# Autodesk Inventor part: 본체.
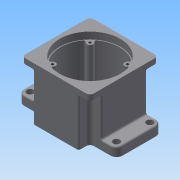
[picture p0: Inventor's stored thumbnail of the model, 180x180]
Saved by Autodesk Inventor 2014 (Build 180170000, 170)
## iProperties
Created: 2015-06
Part Number: 본체.
Material: 일반
Document SubType Name: Modeling
Designer: AMC
Density: 1 g/cm^3
Appearance: 기본값
Author: AMC
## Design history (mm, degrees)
sketch "스케치1"
  geometry: L1 (0, 0)-(30, 0); L2 (30, 0)-(30, 15); L3 (30, 15)-(65, 15); L4 (65, 15)-(65, 75); L5 (65, 75)-(30, 75); L6 (30, 75)-(30, 90); L7 (30, 90)-(0, 90); L8 (0, 90)-(0, 0); L9 (0, 0)-(-30, 0); L10 (-30, 0)-(-30, 15); L11 (-30, 15)-(-65, 15); L12 (-65, 15)-(-65, 75); L13 (-65, 75)-(-30, 75); L14 (-30, 75)-(-30, 90); L15 (-30, 90)-(0, 90)
  constraints: 30 end point, 6 symmetric about line, 5 parallel, 1 collinear, 1 horizontal, 1 perpendicular
  dimensions: "d0" = 130 diameter of L4 L8; "d1" = 60 diameter of L6 L8; "d2" = 60 diameter of L2 L8; "d3" = 60 distance between parallel lines of L5 L3; "d4" = 90 distance between parallel lines of L1 L7; "d5" = 15 distance between parallel lines of L1 L3
extrude "돌출1" new body sketch "스케치1" distance "d6" = 12; taper "d7" = 0 deg
sketch "스케치2"
  geometry: L1 (30, 90)-(-30, 90) reference; L2 (-30, 90)-(-30, 75) reference; L3 (-30, 75)-(-65, 75) reference; L4 (-65, 15)-(-30, 15) reference; L5 (-30, 15)-(-30, 0) reference; L6 (-30, 0)-(30, 0) reference; L7 (30, 0)-(30, 15) reference; L8 (30, 15)-(65, 15) reference; L9 (65, 75)-(30, 75) reference; L10 (30, 75)-(30, 90) reference; L11 (-45, 75)-(-45, 15); L12 (45, 75)-(45, 15); 1 further point
  constraints: 4 end point, 4 point on line, 2 perpendicular
  dimensions: "d8" = 45 distance from line of L12 point (0, 0); "d9" = 90 distance between parallel lines of L11 L12
extrude "돌출2" join sketch "스케치2" distance "d10" = 51; taper "d11" = 0 deg
sketch "스케치3"
  geometry: L1 (-45, 75)-(-45, 15) reference; L2 (-45, 15)-(-30, 15) reference; L3 (30, 0)-(30, 15) reference; L4 (45, 75)-(30, 75) reference; L5 (-45, 90)-(45, 90); L6 (45, 90)-(45, 0); L7 (45, 0)-(-45, 0); L8 (-45, 0)-(-45, 90); 1 further point
  constraints: 8 end point, 2 parallel, 1 horizontal, 1 perpendicular, 1 point on line
  dimensions: "d12" = 15 distance between parallel lines of L2 L7; "d13" = 15 distance between parallel lines of L4 L5; "d14" = 15 distance between parallel lines of L3 L6
extrude "돌출3" join sketch "스케치3" distance "d15" = 7; taper "d16" = 0 deg
sketch "스케치4"
  geometry: L1 (45, 0)-(45, 90) reference; C1 r 40 at (0, 45); 2 further points
  constraints: 1 centre point, 1 midpoint
  dimensions: "d17" = 80 diameter of C1; "d18" = 0 horizontal distance of point (0, 0) C1.centre; "d19" = 0 vertical distance of point (45, 45) C1.centre
extrude "돌출4" cut sketch "스케치4" distance "d20" = 9; taper "d21" = 0 deg
sketch "스케치5"
  geometry: L1 (0, 0)-(24.749, 24.749); L2 (0, 0)-(35, 0); L3 (21.92, 27.577)-(24.603, 30.26); L4 (27.577, 21.92)-(30.26, 24.603); C1 r 40 at (0, 0) reference; A1 r 39 centre (0, 0) between (24.603, 30.26) and (30.26, 24.603); A2 r 4 centre (24.749, 24.749) between (21.92, 27.577) and (27.577, 21.92); 1 further point
  constraints: 8 end point, 4 point on circle, 2 centre point, 2 coincident, 2 parallel, 2 tangent, 1 equal length, 1 horizontal
  dimensions: "d22" = 78 diameter of A1; "d23" = 35 distance of L1.start L1.end; "d24" = 45 deg angle of L2 L1; "d25" = 8 diameter of A2
extrude "돌출5" cut sketch "스케치5" distance "d26" = 52; taper "d27" = 0 deg
extrude "돌출6" join sketch "스케치5" distance "d28" = 52; taper "d29" = 0 deg
fillet "모깎기1" dims "d30" = 2
hole "구멍1" diameter "d33" = 3.459; stored, may be unused: countersink angle "d37" = 90 deg, drill point angle "d39" = 118 deg; dims "d31" = 10, "d32" = 10, "d34" = 12, "d35" = 4, "d36" = 2, "d38" = 15
sketch "스케치6"
  geometry: A1 r 39 centre (0, 0) between (-31.684, 22.74) and (-31.684, -22.74) reference; A2 r 39 centre (0, 0) between (-22.74, -31.684) and (22.74, -31.684) reference; A3 r 20.5 centre (0, 11) between (7.402, -8.117) and (-7.402, -8.117); A4 r 14 centre (0, -20) between (-7.402, -8.117) and (7.402, -8.117); 1 further point
  constraints: 4 point on circle, 2 centre point
  dimensions: "d43" = 41 diameter of A3; "d44" = 0 horizontal distance of A3.centre A1.centre; "d45" = 11 distance of A2.centre A3.centre; "d46" = 28 diameter of A4; "d47" = 0 horizontal distance of A1.centre A4.centre; "d48" = 20 distance of A1.centre A4.centre
extrude "돌출7" join sketch "스케치6" distance "d49" = 7; taper "d50" = 0 deg
sketch "스케치7"
  geometry: L1 (65, 75)-(65, 15) reference; C1 r 25 at (0, 56); 2 further points
  constraints: 1 centre point, 1 midpoint
  dimensions: "d51" = 50 diameter of C1; "d52" = 0 horizontal distance of point (0, 0) C1.centre; "d53" = 11 vertical distance of point (65, 45) C1.centre
extrude "돌출8" join sketch "스케치7" distance "d54" = 7; taper "d55" = 0 deg
sketch "스케치8"
  geometry: L1 (5, 70)-(5, 61) reference; L2 (5, 61)-(6, 61) reference; L3 (6, 61)-(6, 9) reference; L4 (6, 9)-(11, 9) reference; L5 (11, 9)-(11, 16) reference; L6 (11, 16)-(76.5, 16) reference; L7 (76.5, 16)-(76.5, 9) reference; L8 (76.5, 9)-(84, 9) reference; L9 (84, 9)-(84, 61) reference; L10 (84, 61)-(85, 61) reference; L11 (85, 61)-(85, 70) reference; L12 (85, 70)-(90, 70) reference; L13 (90, 70)-(90, 0) reference; L14 (90, 0)-(81, 0) reference; L15 (81, 0)-(81, -7) reference; L16 (81, -7)-(31, -7) reference; L17 (31, -7)-(31, 0) reference; L18 (31, 0)-(0, 0) reference; L19 (0, 0)-(0, 70) reference; L20 (0, 70)-(5, 70) reference; L21 (56, -7)-(56, 16); L22 (72, -7)-(72, 1); L23 (72, 1)-(68.5, 1); L24 (68.5, 1)-(68.5, 6); L25 (68.5, 6)-(73.5, 6); L26 (73.5, 6)-(73.5, 16); L27 (25, 16)-(25, 8); L28 (25, 8)-(34.5, 8); L29 (34.5, 8)-(34.5, 9); L30 (34.5, 9)-(36, 9); L31 (36, 9)-(36, 16)
  constraints: 22 end point, 6 parallel, 5 perpendicular, 5 point on line, 1 midpoint
  dimensions: "d56" = 35 diameter of L26 L21; "d57" = 32 diameter of L22 L21; "d58" = 25 diameter of L24 L21; "d59" = 8 distance between parallel lines of L16 L23; "d60" = 5 distance between parallel lines of L25 L23; "d61" = 14 distance from line of L27.start L5; "d62" = 22 diameter of L31 L27; "d63" = 19 diameter of L29 L27; "d64" = 1 distance between parallel lines of L30 L28; "d65" = 7 distance between parallel lines of L6 L30
  node "절단 모서리 투영1"
revolve "회전1" stored, may be unused: angle "d66" = 90 deg
revolve "회전2" stored, may be unused: angle "d67" = 90 deg
fillet "모깎기2" dims "d68" = 8
sketch "스케치9"
  geometry: L1 (-27.577, 66.92)-(-28.645, 67.988) reference; L2 (-28.645, 22.012)-(-27.577, 23.08) reference; L3 (-21.92, 17.423)-(-22.988, 16.355) reference; L4 (22.988, 16.355)-(21.92, 17.423) reference; L5 (27.577, 23.08)-(28.645, 22.012) reference; L6 (28.645, 67.988)-(27.577, 66.92) reference; L7 (21.92, 72.577)-(22.988, 73.645) reference; L8 (-22.988, 73.645)-(-21.92, 72.577) reference; L9 (30, 90)-(30, 75) reference; L10 (30, 75)-(45, 75) reference; L11 (45, 75)-(45, 15) reference; L12 (45, 15)-(30, 15) reference; L13 (30, 15)-(30, 0) reference; L14 (30, 0)-(-30, 0) reference; L15 (-30, 0)-(-30, 15) reference; L16 (-30, 15)-(-45, 15) reference; L17 (-45, 15)-(-45, 75) reference; L18 (-57, 75)-(-45, 75) reference; L19 (-65, 23)-(-65, 67) reference; L20 (-45, 15)-(-57, 15) reference; L21 (-30, 90)-(30, 90) reference; L22 (-30, 75)-(-30, 90) reference; L23 (-45, 75)-(-30, 75) reference; L24 (45, 75)-(57, 75) reference; L25 (65, 67)-(65, 23) reference; L26 (57, 15)-(45, 15) reference; C1 r 11 at (0, 25) reference; C2 r 17.5 at (0, 56) reference; A1 r 8 centre (57, 67) between (65, 67) and (57, 75) reference; A2 r 8 centre (57, 23) between (57, 15) and (65, 23) reference; A3 r 20.5 centre (0, 56) between (7.402, 36.883) and (-7.402, 36.883) reference; A4 r 14 centre (0, 25) between (-7.402, 36.883) and (7.402, 36.883) reference; A5 r 4 centre (-24.749, 69.749) between (-27.577, 66.92) and (-21.92, 72.577) reference; A6 r 2 centre (-30.059, 66.574) between (-28.645, 67.988) and (-31.684, 67.74) reference; A7 r 39 centre (0, 45) between (-31.684, 67.74) and (-31.684, 22.26) reference; A8 r 2 centre (-30.059, 23.426) between (-31.684, 22.26) and (-28.645, 22.012) reference; A9 r 4 centre (-24.749, 20.251) between (-21.92, 17.423) and (-27.577, 23.08) reference; A10 r 2 centre (-21.574, 14.941) between (-22.988, 16.355) and (-22.74, 13.316) reference; A11 r 39 centre (0, 45) between (-22.74, 13.316) and (22.74, 13.316) reference; A12 r 2 centre (21.574, 14.941) between (22.74, 13.316) and (22.988, 16.355) reference; A13 r 4 centre (24.749, 20.251) between (27.577, 23.08) and (21.92, 17.423) reference; A14 r 2 centre (30.059, 23.426) between (28.645, 22.012) and (31.684, 22.26) reference; A15 r 39 centre (0, 45) between (31.684, 22.26) and (31.684, 67.74) reference; A16 r 2 centre (30.059, 66.574) between (31.684, 67.74) and (28.645, 67.988) reference; A17 r 4 centre (24.749, 69.749) between (21.92, 72.577) and (27.577, 66.92) reference; A18 r 2 centre (21.574, 75.059) between (22.988, 73.645) and (22.74, 76.684) reference; A19 r 39 centre (0, 45) between (22.74, 76.684) and (-22.74, 76.684) reference; A20 r 2 centre (-21.574, 75.059) between (-22.74, 76.684) and (-22.988, 73.645) reference; A21 r 8 centre (-57, 67) between (-57, 75) and (-65, 67) reference; A22 r 8 centre (-57, 23) between (-65, 23) and (-57, 15) reference; A23 r 8 centre (57, 67) between (65, 67) and (57, 75) reference; A24 r 8 centre (57, 23) between (57, 15) and (65, 23) reference; 1 further point
hole "구멍2" sketch "스케치9" at (-57, 67), (-57, 23), (57, 23), (57, 67) diameter "d69" = 9; stored, may be unused: countersink angle "d73" = 90 deg, drill point angle "d75" = 118 deg; dims "d70" = 12, "d71" = 4, "d72" = 2, "d74" = 15
fillet "모깎기3" dims "d76" = 5, "d77" = 2
fillet "모깎기4" dims "d78" = 2, "d79" = 5
fillet "모깎기5" dims "d80" = 2
fillet "모깎기6" dims "d81" = 2
fillet "모깎기7" dims "d82" = 0.3
fillet "모깎기8" dims "d83" = 1
chamfer "모따기1" distance "d84" = 1; stored, may be unused: second distance "d85" = 2, angle "d86" = 45 deg
node "솔리드1"
pattern_circular "원형 패턴1" dims "d41" = 360 deg
node "절단 모서리 투영2"
